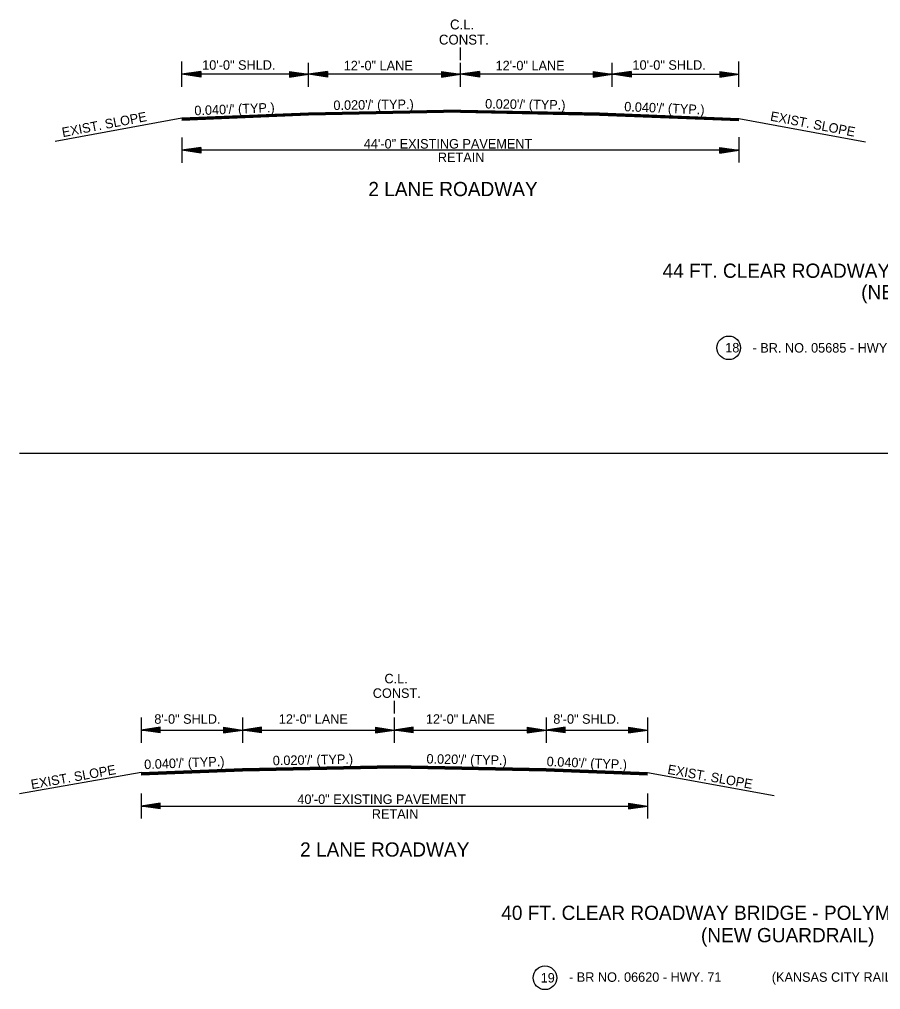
# Model space of a CAD drawing. Extents: x 545241 to 1930787, y -1971772 to 596640.
# Drawn here: x 546719 to 547399, y -1956083 to -1955317 of the extents above; entities that cross this region are included whole.
import ezdxf

# ---------------------------------------------------------------- set-up
doc = ezdxf.new("R2010")
doc.units = 0
doc.layers.add('R_Border', color=7, linetype='Continuous')
doc.layers.add('R_Draft', color=7, linetype='Continuous')

# ---------------------------------------------------------------- blocks, each defined once
blk = doc.blocks.new('ARROW')
at = {"layer": 'R_Draft'}
for p, q in [((-2, 0.3), (0, 0)), ((-2, 0.3), (-2, -0.3)), ((-2, 0.25), (-0.334, 0)), ((-2, 0.199), (-0.678, 0)), ((-2, 0.149), (-1.011, 0)), ((-2, 0.097), (-1.35, 0)), ((-2, 0.047), (-1.684, 0)), ((-2, -0.3), (0, 0)), ((-2, -0.098), (-1.35, 0)), ((-2, -0.199), (-0.678, 0)), ((-2, -0.25), (-0.334, 0)), ((-2, -0.149), (-1.011, 0)), ((-2, -0.047), (-1.684, 0))]:
    blk.add_line(p, q, dxfattribs=at)
blk = doc.blocks.new('BPPOLY')
at = {"layer": 'R_Border'}
blk.add_circle((0, 0), 9.34, dxfattribs=at)

msp = doc.modelspace()

# ---------------------------------------------------------------- linework, layer by layer
at = {"layer": 'R_Border'}
for p, q in [((546947.29, -1955390.75), (546847.29, -1955394.75)), ((546947.29, -1955391.05), (546847.29, -1955395.05)), ((546947.29, -1955391.35), (546847.29, -1955395.35)), ((546947.29, -1955391.65), (546847.29, -1955395.65)), ((546947.29, -1955391.95), (546847.29, -1955395.95)), ((546947.29, -1955392.25), (546847.29, -1955396.25)), ((546947.29, -1955392.42), (546847.29, -1955396.42)), ((547177.29, -1955390.55), (547287.29, -1955394.95)), ((547177.29, -1955390.85), (547287.29, -1955395.25)), ((547177.29, -1955391.15), (547287.29, -1955395.55)), ((547177.29, -1955391.45), (547287.29, -1955395.85)), ((547177.29, -1955391.75), (547287.29, -1955396.15)), ((547177.29, -1955392.05), (547287.29, -1955396.45)), ((547177.29, -1955392.22), (547287.29, -1955396.62)), ((546718.93, -1955659.48), (547746.88, -1955659.48)), ((547015.08, -1955855.32), (547015.08, -1955865.32)), ((546815.08, -1955868.32), (546815.08, -1955888.32)), ((546895.08, -1955868.32), (546895.08, -1955888.32)), ((547015.08, -1955868.32), (547015.08, -1955888.32)), ((547135.08, -1955868.32), (547135.08, -1955888.32)), ((547215.08, -1955868.32), (547215.08, -1955888.32)), ((546815.08, -1955878.32), (547215.08, -1955878.32)), ((546815.08, -1955911.92), (546718.85, -1955928.62)), ((547215.08, -1955911.92), (547315.08, -1955929.92)), ((546815.08, -1955928.32), (546815.08, -1955948.32)), ((547215.08, -1955928.32), (547215.08, -1955948.32)), ((546815.08, -1955938.32), (547215.08, -1955938.32))]:
    msp.add_line(p, q, dxfattribs=at)
for points in [[(546815.08, -1955911.92), (546895.08, -1955908.72), (547015.08, -1955906.32), (547135.08, -1955908.72), (547215.08, -1955911.92)], [(546815.08, -1955912.22), (546895.08, -1955909.02), (547015.08, -1955906.62), (547135.08, -1955909.02), (547215.08, -1955912.22)], [(546815.08, -1955912.52), (546895.08, -1955909.32), (547015.08, -1955906.92), (547135.08, -1955909.32), (547215.08, -1955912.52)], [(546815.08, -1955912.82), (546895.08, -1955909.62), (547015.08, -1955907.22), (547135.08, -1955909.62), (547215.08, -1955912.82)], [(546815.08, -1955913.12), (546895.08, -1955909.92), (547015.08, -1955907.52), (547135.08, -1955909.92), (547215.08, -1955913.12)], [(546815.08, -1955913.42), (546895.08, -1955910.22), (547015.08, -1955907.82), (547135.08, -1955910.22), (547215.08, -1955913.42)], [(546815.08, -1955913.72), (546895.08, -1955910.52), (547015.08, -1955908.12), (547135.08, -1955910.52), (547215.08, -1955913.72)]]:
    msp.add_lwpolyline(points, dxfattribs=at)
msp.add_circle((547279.31, -1955576.21), 9.34, dxfattribs=at)
at = {"layer": 'R_Draft'}
for p, q in [((547067.29, -1955348.73), (547067.29, -1955338.73)), ((546847.29, -1955370.04), (546847.29, -1955350.04)), ((546947.29, -1955370.04), (546947.29, -1955350.85)), ((547067.29, -1955370.04), (547067.29, -1955350.85)), ((547187.29, -1955370.04), (547187.29, -1955350.85)), ((547287.29, -1955370.04), (547287.29, -1955350.04)), ((546862.29, -1955357.79), (546847.29, -1955360.04)), ((546947.29, -1955360.04), (546847.29, -1955360.04)), ((546862.29, -1955362.29), (546847.29, -1955360.04)), ((546862.29, -1955358.17), (546849.79, -1955360.04)), ((546862.29, -1955361.92), (546849.79, -1955360.04)), ((546862.29, -1955358.55), (546852.37, -1955360.04)), ((546862.29, -1955361.53), (546852.37, -1955360.04)), ((546862.29, -1955358.92), (546854.87, -1955360.04)), ((546862.29, -1955361.16), (546854.87, -1955360.04)), ((546862.29, -1955359.31), (546857.41, -1955360.04)), ((546862.29, -1955360.78), (546857.41, -1955360.04)), ((546862.29, -1955359.69), (546859.92, -1955360.04)), ((546862.29, -1955360.39), (546859.92, -1955360.04)), ((546862.29, -1955357.79), (546862.29, -1955362.29)), ((546932.29, -1955357.79), (546947.29, -1955360.04)), ((546932.29, -1955357.79), (546932.29, -1955362.29)), ((546932.29, -1955358.17), (546944.78, -1955360.04)), ((546932.29, -1955358.55), (546942.2, -1955360.04)), ((546932.29, -1955358.92), (546939.7, -1955360.04)), ((546932.29, -1955359.31), (546937.16, -1955360.04)), ((546932.29, -1955359.69), (546934.66, -1955360.04)), ((546932.29, -1955362.29), (546947.29, -1955360.04)), ((546932.29, -1955360.78), (546937.16, -1955360.04)), ((546932.29, -1955361.53), (546942.2, -1955360.04)), ((546932.29, -1955361.92), (546944.78, -1955360.04)), ((546932.29, -1955361.16), (546939.7, -1955360.04)), ((546932.29, -1955360.39), (546934.66, -1955360.04)), ((546962.29, -1955357.79), (546947.29, -1955360.04)), ((547067.29, -1955360.04), (546947.29, -1955360.04)), ((546962.29, -1955362.29), (546947.29, -1955360.04)), ((546962.29, -1955358.17), (546949.79, -1955360.04)), ((546962.29, -1955361.92), (546949.79, -1955360.04)), ((546962.29, -1955358.55), (546952.37, -1955360.04)), ((546962.29, -1955361.53), (546952.37, -1955360.04)), ((546962.29, -1955358.92), (546954.87, -1955360.04)), ((546962.29, -1955361.16), (546954.87, -1955360.04)), ((546962.29, -1955359.31), (546957.41, -1955360.04)), ((546962.29, -1955360.78), (546957.41, -1955360.04)), ((546962.29, -1955359.69), (546959.92, -1955360.04)), ((546962.29, -1955360.39), (546959.92, -1955360.04)), ((546962.29, -1955357.79), (546962.29, -1955362.29)), ((547052.29, -1955357.79), (547067.29, -1955360.04)), ((547052.29, -1955357.79), (547052.29, -1955362.29)), ((547052.29, -1955358.17), (547064.78, -1955360.04)), ((547052.29, -1955358.55), (547062.2, -1955360.04)), ((547052.29, -1955358.92), (547059.7, -1955360.04)), ((547052.29, -1955359.31), (547057.16, -1955360.04)), ((547052.29, -1955359.69), (547054.66, -1955360.04)), ((547052.29, -1955362.29), (547067.29, -1955360.04)), ((547052.29, -1955360.78), (547057.16, -1955360.04)), ((547052.29, -1955361.53), (547062.2, -1955360.04)), ((547052.29, -1955361.92), (547064.78, -1955360.04)), ((547052.29, -1955361.16), (547059.7, -1955360.04)), ((547052.29, -1955360.39), (547054.66, -1955360.04)), ((547082.29, -1955357.79), (547067.29, -1955360.04)), ((547187.29, -1955360.04), (547067.29, -1955360.04)), ((547082.29, -1955362.29), (547067.29, -1955360.04)), ((547082.29, -1955358.17), (547069.79, -1955360.04)), ((547082.29, -1955361.92), (547069.79, -1955360.04)), ((547082.29, -1955358.55), (547072.37, -1955360.04)), ((547082.29, -1955361.53), (547072.37, -1955360.04)), ((547082.29, -1955358.92), (547074.87, -1955360.04)), ((547082.29, -1955361.16), (547074.87, -1955360.04)), ((547082.29, -1955359.31), (547077.41, -1955360.04)), ((547082.29, -1955360.78), (547077.41, -1955360.04)), ((547082.29, -1955359.69), (547079.92, -1955360.04)), ((547082.29, -1955360.39), (547079.92, -1955360.04)), ((547082.29, -1955357.79), (547082.29, -1955362.29)), ((547172.29, -1955357.79), (547187.29, -1955360.04)), ((547172.29, -1955357.79), (547172.29, -1955362.29)), ((547172.29, -1955358.17), (547184.78, -1955360.04)), ((547172.29, -1955358.55), (547182.2, -1955360.04)), ((547172.29, -1955358.92), (547179.7, -1955360.04)), ((547172.29, -1955359.31), (547177.16, -1955360.04)), ((547172.29, -1955359.69), (547174.66, -1955360.04)), ((547172.29, -1955362.29), (547187.29, -1955360.04)), ((547172.29, -1955360.78), (547177.16, -1955360.04)), ((547172.29, -1955361.53), (547182.2, -1955360.04)), ((547172.29, -1955361.92), (547184.78, -1955360.04)), ((547172.29, -1955361.16), (547179.7, -1955360.04)), ((547172.29, -1955360.39), (547174.66, -1955360.04)), ((547202.29, -1955357.79), (547187.29, -1955360.04)), ((547187.29, -1955360.04), (547287.29, -1955360.04)), ((547202.29, -1955362.29), (547187.29, -1955360.04)), ((547202.29, -1955358.17), (547189.79, -1955360.04)), ((547202.29, -1955361.92), (547189.79, -1955360.04)), ((547202.29, -1955358.55), (547192.37, -1955360.04)), ((547202.29, -1955361.53), (547192.37, -1955360.04)), ((547202.29, -1955358.92), (547194.87, -1955360.04)), ((547202.29, -1955361.16), (547194.87, -1955360.04)), ((547202.29, -1955359.31), (547197.41, -1955360.04)), ((547202.29, -1955360.78), (547197.41, -1955360.04)), ((547202.29, -1955359.69), (547199.92, -1955360.04)), ((547202.29, -1955360.39), (547199.92, -1955360.04)), ((547202.29, -1955357.79), (547202.29, -1955362.29)), ((547272.29, -1955357.79), (547287.29, -1955360.04)), ((547272.29, -1955357.79), (547272.29, -1955362.29)), ((547272.29, -1955358.17), (547284.78, -1955360.04)), ((547272.29, -1955358.55), (547282.2, -1955360.04)), ((547272.29, -1955358.92), (547279.7, -1955360.04)), ((547272.29, -1955359.31), (547277.16, -1955360.04)), ((547272.29, -1955359.69), (547274.66, -1955360.04)), ((547272.29, -1955362.29), (547287.29, -1955360.04)), ((547272.29, -1955360.78), (547277.16, -1955360.04)), ((547272.29, -1955361.53), (547282.2, -1955360.04)), ((547272.29, -1955361.92), (547284.78, -1955360.04)), ((547272.29, -1955361.16), (547279.7, -1955360.04)), ((547272.29, -1955360.39), (547274.66, -1955360.04)), ((547067.29, -1955388.35), (546947.29, -1955390.75)), ((547067.29, -1955388.65), (546947.29, -1955391.05)), ((547067.29, -1955388.95), (546947.29, -1955391.35)), ((547067.29, -1955389.25), (546947.29, -1955391.65)), ((547067.29, -1955389.55), (546947.29, -1955391.95)), ((547067.29, -1955389.85), (546947.29, -1955392.25)), ((547067.29, -1955390.02), (546947.29, -1955392.42)), ((547067.29, -1955388.35), (547177.29, -1955390.55)), ((547067.29, -1955388.65), (547177.29, -1955390.85)), ((547067.29, -1955388.95), (547177.29, -1955391.15)), ((547067.29, -1955389.25), (547177.29, -1955391.45)), ((547067.29, -1955389.55), (547177.29, -1955391.75)), ((547067.29, -1955389.85), (547177.29, -1955392.05)), ((547067.29, -1955390.02), (547177.29, -1955392.22)), ((546847.29, -1955394.75), (546747.22, -1955413.13)), ((547287.29, -1955394.95), (547387.35, -1955413.33)), ((546847.29, -1955410.01), (546847.29, -1955430.01)), ((547287.29, -1955409.76), (547287.29, -1955429.76)), ((546862.29, -1955417.76), (546847.29, -1955420.01)), ((546862.29, -1955422.26), (546847.29, -1955420.01)), ((547287.29, -1955420.01), (546847.29, -1955420.01)), ((546862.29, -1955418.13), (546849.79, -1955420.01)), ((546862.29, -1955421.88), (546849.79, -1955420.01)), ((546862.29, -1955418.52), (546852.37, -1955420.01)), ((546862.29, -1955421.5), (546852.37, -1955420.01)), ((546862.29, -1955418.89), (546854.87, -1955420.01)), ((546862.29, -1955421.13), (546854.87, -1955420.01)), ((546862.29, -1955419.28), (546857.41, -1955420.01)), ((546862.29, -1955420.74), (546857.41, -1955420.01)), ((546862.29, -1955419.66), (546859.92, -1955420.01)), ((546862.29, -1955420.36), (546859.92, -1955420.01)), ((546862.29, -1955417.76), (546862.29, -1955422.26)), ((547272.29, -1955417.76), (547287.29, -1955420.01)), ((547272.29, -1955422.26), (547272.29, -1955417.76)), ((547272.29, -1955418.13), (547284.78, -1955420.01)), ((547272.29, -1955418.52), (547282.2, -1955420.01)), ((547272.29, -1955418.89), (547279.7, -1955420.01)), ((547272.29, -1955419.27), (547277.16, -1955420.01)), ((547272.29, -1955419.66), (547274.66, -1955420.01)), ((547272.29, -1955422.26), (547287.29, -1955420.01)), ((547272.29, -1955420.74), (547277.16, -1955420.01)), ((547272.29, -1955421.5), (547282.2, -1955420.01)), ((547272.29, -1955421.88), (547284.78, -1955420.01)), ((547272.29, -1955421.13), (547279.7, -1955420.01)), ((547272.29, -1955420.36), (547274.66, -1955420.01))]:
    msp.add_line(p, q, dxfattribs=at)

# ---------------------------------------------------------------- block references
at = {"layer": 'R_Border', "xscale": 7.5, "yscale": 7.5, "rotation": 180}
for p in [(546815.08, -1955878.32), (546895.08, -1955878.32), (547015.08, -1955878.32), (547135.08, -1955878.32), (546815.08, -1955938.32)]:
    msp.add_blockref('ARROW', p, dxfattribs=at)
at = {"layer": 'R_Border', "xscale": 7.5, "yscale": 7.5}
for p in [(546895.08, -1955878.32), (547015.08, -1955878.32), (547135.08, -1955878.32), (547215.08, -1955878.32), (547215.08, -1955938.32)]:
    msp.add_blockref('ARROW', p, dxfattribs=at)
at = {"layer": 'R_Border'}
msp.add_blockref('BPPOLY', (547134.1, -1956074.08), dxfattribs=at)

# ---------------------------------------------------------------- texts
for s, height, p in [('C.L.', 7.5, (547007.27, -1955841.36)), ('CONST.', 7.5, (546998.06, -1955852.86)), ('8\'-0" SHLD.', 7.5, (546825.45, -1955873.32)), ('12\'-0" LANE', 7.5, (546923.83, -1955873.32)), ('12\'-0" LANE', 7.5, (547040.02, -1955873.32)), ('8\'-0" SHLD.', 7.5, (547140.67, -1955873.32)), ('40\'-0" EXISTING PAVEMENT', 7.5, (546938.46, -1955936.71)), ('RETAIN', 7.5, (546997.28, -1955948.33)), ('2 LANE ROADWAY', 11.25, (546940.64, -1955978.32)), ('40 FT. CLEAR ROADWAY BRIDGE - POLYMER OVERLAY', 11.25, (547099.57, -1956028.36)), ('(NEW GUARDRAIL)', 11.25, (547257.34, -1956045.99)), ('19', 7.5, (547130.7, -1956077.83)), ('- BR NO. 06620 - HWY. 71', 7.5, (547153.1, -1956077.26))]:
    msp.add_text(s, height=height, dxfattribs=at).set_placement(p)
for s, rotation, p in [("0.040'/' (TYP.)", 2.2916, (546817.59, -1955909.22)), ("0.020'/' (TYP.)", 1.1458, (546919.1, -1955906.16)), ("0.020'/' (TYP.)", 358.8542, (547040.42, -1955904.71)), ("0.040'/' (TYP.)", 357.7084, (547135.33, -1955906.79)), ('EXIST. SLOPE', 10.204, (546728.63, -1955925.07)), ('EXIST. SLOPE', 349.796, (547230.52, -1955912.81))]:
    msp.add_text(s, height=7.5, rotation=rotation, dxfattribs=at).set_placement(p)
at = {"layer": 'R_Draft'}
for s, height, p in [('C.L.', 7.8, (547059.1, -1955324.56)), ('CONST.', 7.8, (547050.32, -1955336.52)), ('10\'-0" SHLD.', 7.5, (546863.27, -1955356.44)), ('12\'-0" LANE', 7.5, (546975.1, -1955356.87)), ('12\'-0" LANE', 7.5, (547095.1, -1955356.87)), ('10\'-0" SHLD.', 7.5, (547203.27, -1955356.44)), ('44\'-0" EXISTING PAVEMENT', 7.5, (546990.96, -1955418.69)), ('RETAIN', 7.5, (547049.48, -1955429.41)), ('2 LANE ROADWAY', 11.25, (546994.56, -1955456.33)), ('44 FT. CLEAR ROADWAY BRIDGE - POLYMER OVERLAY', 11.25, (547227.07, -1955520.88)), ('(NEW GUARDRAIL)', 11.25, (547383.95, -1955537.76)), ('18', 7.5, (547276.54, -1955579.85)), ('- BR. NO. 05685 - HWY. 41 (D & E RAILROAD OVERPASS)', 7.5, (547298.11, -1955579.96)), ('(KANSAS CITY RAILROAD OVERPASS)', 7.5, (547313.3, -1956077.26))]:
    msp.add_text(s, height=height, dxfattribs=at).set_placement(p)
for s, rotation, p in [("0.040'/' (TYP.)", 2.29061, (546857.22, -1955392.46)), ("0.020'/' (TYP.)", 0.87191, (546967.01, -1955388.26)), ("0.020'/' (TYP.)", 359.12809, (547086.78, -1955387.03)), ("0.040'/' (TYP.)", 357.70939, (547196.62, -1955389.23)), ('EXIST. SLOPE', 10.88286, (546753.2, -1955409.75)), ('EXIST. SLOPE', 349.11714, (547311.67, -1955396.55))]:
    msp.add_text(s, height=7.5, rotation=rotation, dxfattribs=at).set_placement(p)

doc.saveas('drawing.dxf')
